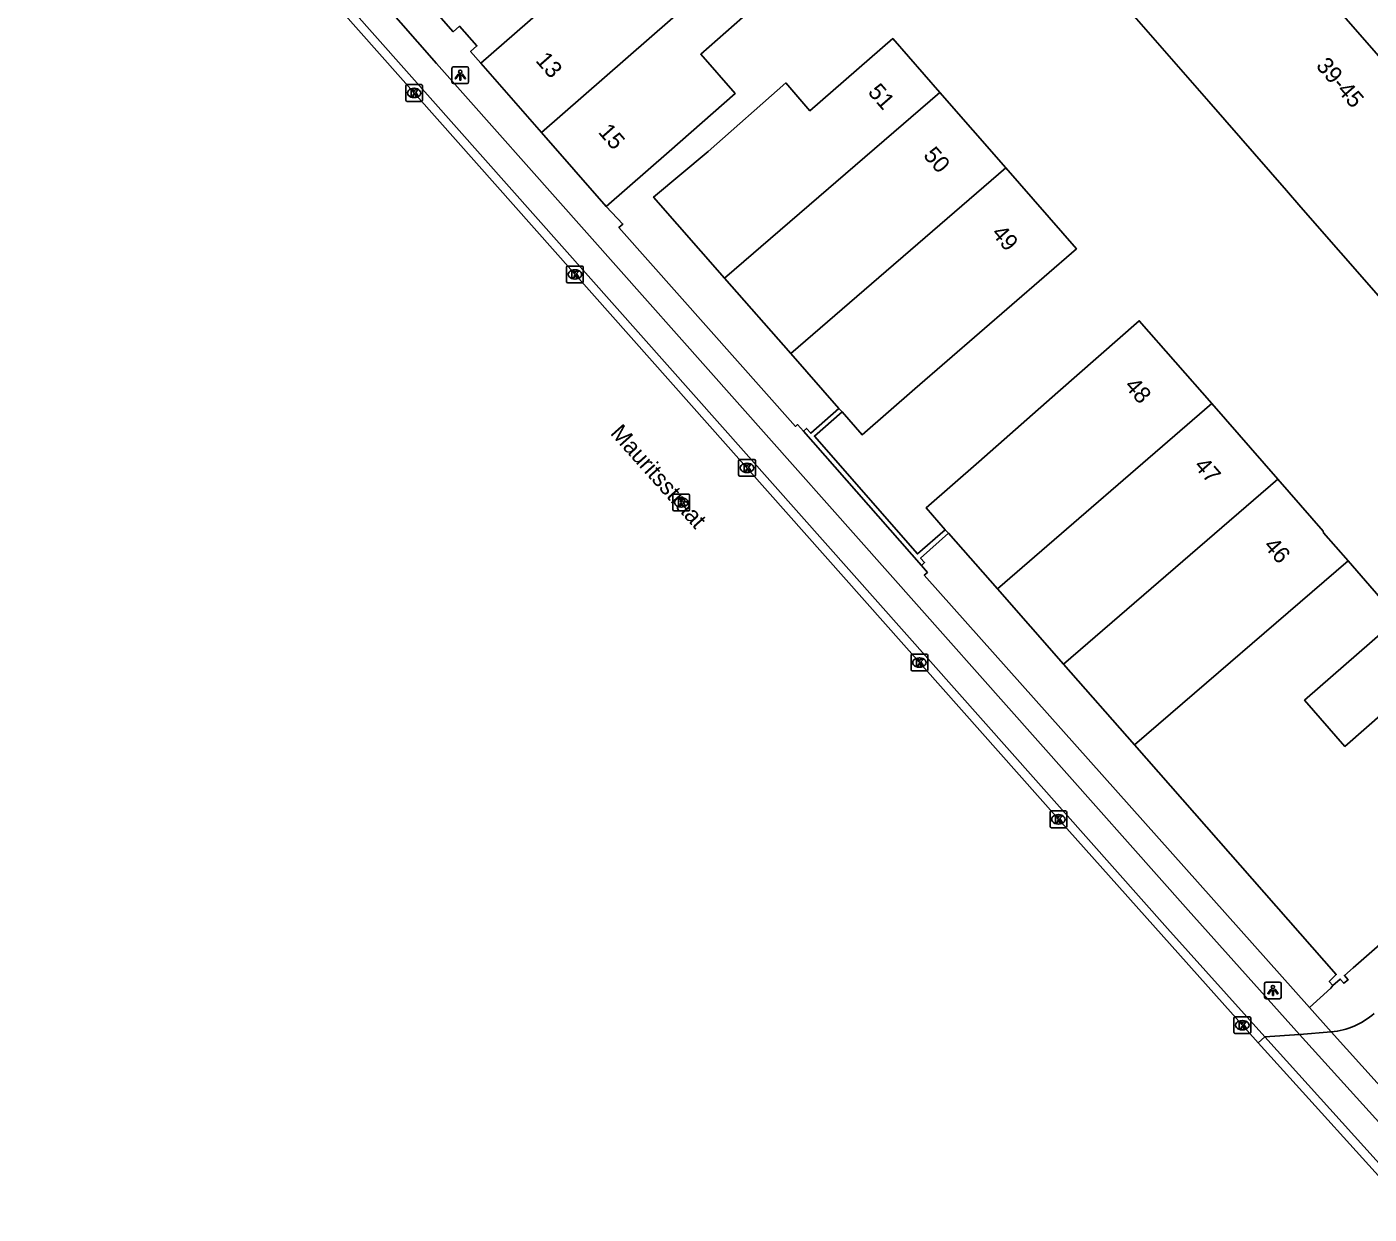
# Model space of a CAD drawing. Extents: x 160664 to 161506, y 382245 to 383288.
# Drawn here: x 160694.2 to 160774.6, y 383018.1 to 383089.2 of the extents above; entities that cross this region are included whole.
import ezdxf

# ---------------------------------------------------------------- set-up
doc = ezdxf.new("R2010")
doc.units = 0
for name, color, linetype in [('IMGEO_Berm_gesloten', 7, 'Continuous'), ('IMGEO_Fietspad_gesloten', 7, 'Continuous'), ('IMGEO_Kolk', 7, 'Continuous'), ('IMGEO_Lichtpunt', 7, 'Continuous'), ('IMGEO_Muur', 7, 'Continuous'), ('IMGEO_Openbare_ruimte_label', 7, 'Continuous'), ('IMGEO_Pand', 7, 'Continuous'), ('IMGEO_Pand_nummerreeks', 7, 'Continuous'), ('IMGEO_Rijbaan_lokaal_gesloten', 7, 'Continuous'), ('IMGEO_Rijbaan_lokaal_open', 7, 'Continuous'), ('IMGEO_Rioolput', 7, 'Continuous'), ('IMGEO_Voetpad_open', 7, 'Continuous')]:
    doc.layers.add(name, color=color, linetype=linetype)

msp = doc.modelspace()

# ---------------------------------------------------------------- linework, layer by layer
at = {"layer": 'IMGEO_Berm_gesloten'}
msp.add_lwpolyline([(160768.358, 383028.694), (160767.962, 383028.335)], dxfattribs=at)
at = {"layer": 'IMGEO_Fietspad_gesloten'}
for points in [[(160770.443, 383028.844), (160763.764, 383036.278), (160718.771, 383086.968), (160703.534, 383104.351), (160702.367, 383105.793), (160696.071, 383113.574)], [(160768.358, 383028.694), (160762.53, 383035.176), (160707.345, 383097.37), (160702.219, 383103.325), (160701.082, 383104.713), (160699.114, 383107.117), (160694.239, 383113.304)], [(160770.443, 383028.844), (160768.358, 383028.694)], [(160777.628, 383018.442), (160768.358, 383028.694)], [(160770.443, 383028.844), (160777.267, 383021.287)]]:
    msp.add_lwpolyline(points, dxfattribs=at)
at = {"layer": 'IMGEO_Kolk'}
for p, q in [((160716.927, 383084.785), (160716.927, 383085.637)), ((160717.002, 383085.711), (160717.854, 383085.711)), ((160717.415, 383085.491), (160717.44, 383085.491)), ((160717.928, 383085.637), (160717.928, 383084.785)), ((160717.854, 383084.711), (160717.002, 383084.711)), ((160717.438, 383084.931), (160717.413, 383084.931)), ((160726.629, 383074.851), (160727.481, 383074.851)), ((160726.554, 383073.925), (160726.554, 383074.777)), ((160727.065, 383074.071), (160727.04, 383074.071)), ((160727.042, 383074.631), (160727.067, 383074.631)), ((160727.555, 383074.777), (160727.555, 383073.925)), ((160727.481, 383073.851), (160726.629, 383073.851)), ((160736.856, 383062.34), (160736.856, 383063.192)), ((160736.931, 383063.266), (160737.783, 383063.266)), ((160737.344, 383063.046), (160737.369, 383063.046)), ((160737.857, 383063.192), (160737.857, 383062.34)), ((160737.783, 383062.266), (160736.931, 383062.266)), ((160737.367, 383062.486), (160737.342, 383062.486)), ((160747.18, 383050.681), (160747.18, 383051.533)), ((160747.255, 383051.607), (160748.107, 383051.607)), ((160748.181, 383051.533), (160748.181, 383050.681)), ((160747.691, 383050.827), (160747.666, 383050.827)), ((160747.668, 383051.387), (160747.693, 383051.387)), ((160748.107, 383050.607), (160747.255, 383050.607)), ((160755.501, 383041.295), (160755.501, 383042.147)), ((160755.576, 383042.221), (160756.428, 383042.221)), ((160755.989, 383042.001), (160756.014, 383042.001)), ((160756.502, 383042.147), (160756.502, 383041.295)), ((160756.428, 383041.221), (160755.576, 383041.221)), ((160756.012, 383041.441), (160755.987, 383041.441)), ((160766.511, 383028.967), (160766.511, 383029.819)), ((160766.586, 383029.893), (160767.438, 383029.893)), ((160767.512, 383029.819), (160767.512, 383028.967)), ((160767.022, 383029.113), (160766.997, 383029.113)), ((160766.999, 383029.673), (160767.024, 383029.673)), ((160767.438, 383028.893), (160766.586, 383028.893))]:
    msp.add_line(p, q, dxfattribs=at)
for points in [[(160716.927, 383084.785), (160716.927, 383085.637)], [(160717.002, 383085.711), (160717.854, 383085.711)], [(160717.248, 383085.411), (160717.371, 383085.411), (160717.371, 383085.26), (160717.501, 383085.411), (160717.665, 383085.411), (160717.519, 383085.26), (160717.672, 383085.011), (160717.52, 383085.011), (160717.435, 383085.175), (160717.371, 383085.108), (160717.371, 383085.011), (160717.248, 383085.011), (160717.248, 383085.411)], [(160717.928, 383085.637), (160717.928, 383084.785)], [(160717.854, 383084.711), (160717.002, 383084.711)], [(160726.629, 383074.851), (160727.481, 383074.851)], [(160726.554, 383073.925), (160726.554, 383074.777)], [(160726.875, 383074.551), (160726.998, 383074.551), (160726.998, 383074.4), (160727.128, 383074.551), (160727.292, 383074.551), (160727.146, 383074.4), (160727.299, 383074.151), (160727.147, 383074.151), (160727.062, 383074.315), (160726.998, 383074.248), (160726.998, 383074.151), (160726.875, 383074.151), (160726.875, 383074.551)], [(160727.555, 383074.777), (160727.555, 383073.925)], [(160727.481, 383073.851), (160726.629, 383073.851)], [(160736.856, 383062.34), (160736.856, 383063.192)], [(160736.931, 383063.266), (160737.783, 383063.266)], [(160737.177, 383062.966), (160737.3, 383062.966), (160737.3, 383062.815), (160737.43, 383062.966), (160737.594, 383062.966), (160737.448, 383062.815), (160737.601, 383062.566), (160737.449, 383062.566), (160737.364, 383062.73), (160737.3, 383062.663), (160737.3, 383062.566), (160737.177, 383062.566), (160737.177, 383062.966)], [(160737.857, 383063.192), (160737.857, 383062.34)], [(160737.783, 383062.266), (160736.931, 383062.266)], [(160747.18, 383050.681), (160747.18, 383051.533)], [(160747.255, 383051.607), (160748.107, 383051.607)], [(160748.181, 383051.533), (160748.181, 383050.681)], [(160747.501, 383051.307), (160747.624, 383051.307), (160747.624, 383051.156), (160747.754, 383051.307), (160747.918, 383051.307), (160747.772, 383051.156), (160747.925, 383050.907), (160747.773, 383050.907), (160747.688, 383051.071), (160747.624, 383051.004), (160747.624, 383050.907), (160747.501, 383050.907), (160747.501, 383051.307)], [(160748.107, 383050.607), (160747.255, 383050.607)], [(160755.501, 383041.295), (160755.501, 383042.147)], [(160755.576, 383042.221), (160756.428, 383042.221)], [(160755.822, 383041.921), (160755.945, 383041.921), (160755.945, 383041.77), (160756.075, 383041.921), (160756.239, 383041.921), (160756.093, 383041.77), (160756.246, 383041.521), (160756.094, 383041.521), (160756.009, 383041.685), (160755.945, 383041.618), (160755.945, 383041.521), (160755.822, 383041.521), (160755.822, 383041.921)], [(160756.502, 383042.147), (160756.502, 383041.295)], [(160756.428, 383041.221), (160755.576, 383041.221)], [(160766.511, 383028.967), (160766.511, 383029.819)], [(160766.586, 383029.893), (160767.438, 383029.893)], [(160767.512, 383029.819), (160767.512, 383028.967)], [(160766.832, 383029.593), (160766.955, 383029.593), (160766.955, 383029.442), (160767.085, 383029.593), (160767.249, 383029.593), (160767.103, 383029.442), (160767.256, 383029.193), (160767.104, 383029.193), (160767.019, 383029.357), (160766.955, 383029.29), (160766.955, 383029.193), (160766.832, 383029.193), (160766.832, 383029.593)], [(160767.438, 383028.893), (160766.586, 383028.893)]]:
    msp.add_lwpolyline(points, dxfattribs=at)
for centre, start, end in [((160717.004, 383085.635), 91.55205, 178.44795), ((160717.004, 383085.635), 91.55205, 178.44795), ((160717.852, 383085.635), 1.55205, 88.44795), ((160717.852, 383085.635), 1.55205, 88.44795), ((160717.004, 383084.787), 181.55205, 268.44795), ((160717.004, 383084.787), 181.55205, 268.44795), ((160717.852, 383084.787), 271.55205, 358.44795), ((160717.852, 383084.787), 271.55205, 358.44795), ((160726.631, 383074.775), 91.55205, 178.44795), ((160726.631, 383074.775), 91.55205, 178.44795), ((160727.479, 383074.775), 1.55205, 88.44795), ((160727.479, 383074.775), 1.55205, 88.44795), ((160726.631, 383073.927), 181.55205, 268.44795), ((160726.631, 383073.927), 181.55205, 268.44795), ((160727.479, 383073.927), 271.55205, 358.44795), ((160727.479, 383073.927), 271.55205, 358.44795), ((160736.933, 383063.19), 91.55205, 178.44795), ((160736.933, 383063.19), 91.55205, 178.44795), ((160737.781, 383063.19), 1.55205, 88.44795), ((160737.781, 383063.19), 1.55205, 88.44795), ((160736.933, 383062.342), 181.55205, 268.44795), ((160736.933, 383062.342), 181.55205, 268.44795), ((160737.781, 383062.342), 271.55205, 358.44795), ((160737.781, 383062.342), 271.55205, 358.44795), ((160747.257, 383051.531), 91.55205, 178.44795), ((160747.257, 383051.531), 91.55205, 178.44795), ((160748.105, 383051.531), 1.55205, 88.44795), ((160748.105, 383051.531), 1.55205, 88.44795), ((160747.257, 383050.683), 181.55205, 268.44795), ((160747.257, 383050.683), 181.55205, 268.44795), ((160748.105, 383050.683), 271.55205, 358.44795), ((160748.105, 383050.683), 271.55205, 358.44795), ((160755.578, 383042.145), 91.55205, 178.44795), ((160755.578, 383042.145), 91.55205, 178.44795), ((160756.426, 383042.145), 1.55205, 88.44795), ((160756.426, 383042.145), 1.55205, 88.44795), ((160755.578, 383041.297), 181.55205, 268.44795), ((160755.578, 383041.297), 181.55205, 268.44795), ((160756.426, 383041.297), 271.55205, 358.44795), ((160756.426, 383041.297), 271.55205, 358.44795), ((160766.588, 383029.817), 91.55205, 178.44795), ((160766.588, 383029.817), 91.55205, 178.44795), ((160767.436, 383029.817), 1.55205, 88.44795), ((160767.436, 383029.817), 1.55205, 88.44795), ((160766.588, 383028.969), 181.55205, 268.44795), ((160766.588, 383028.969), 181.55205, 268.44795), ((160767.436, 383028.969), 271.55205, 358.44795), ((160767.436, 383028.969), 271.55205, 358.44795)]:
    msp.add_arc(centre, 0.0765, start, end, dxfattribs=at)
for centre, major_axis, ratio, start_param, end_param in [((160717.414, 383085.211), (-0.387, 0.002), 0.722429, 4.712389, 7.853982), ((160717.439, 383085.211), (-0.39, 0.002), 0.717154, 1.570796, 4.712389), ((160727.041, 383074.351), (-0.387, 0.002), 0.722429, 4.712389, 7.853982), ((160727.066, 383074.351), (-0.39, 0.002), 0.717154, 1.570796, 4.712389), ((160737.343, 383062.766), (-0.387, 0.002), 0.722429, 4.712389, 7.853982), ((160737.368, 383062.766), (-0.39, 0.002), 0.717154, 1.570796, 4.712389), ((160747.667, 383051.107), (-0.387, 0.002), 0.722429, 4.712389, 7.853982), ((160747.692, 383051.107), (-0.39, 0.002), 0.717154, 1.570796, 4.712389), ((160755.988, 383041.721), (-0.387, 0.002), 0.722429, 4.712389, 7.853982), ((160756.013, 383041.721), (-0.39, 0.002), 0.717154, 1.570796, 4.712389), ((160766.998, 383029.393), (-0.387, 0.002), 0.722429, 4.712389, 7.853982), ((160767.023, 383029.393), (-0.39, 0.002), 0.717154, 1.570796, 4.712389)]:
    msp.add_ellipse(centre, major_axis=major_axis, ratio=ratio, start_param=start_param, end_param=end_param, dxfattribs=at)
at = {"layer": 'IMGEO_Lichtpunt'}
for p, q in [((160719.691, 383086.682), (160719.691, 383085.875)), ((160719.691, 383086.682), (160719.691, 383085.875)), ((160720.593, 383086.777), (160719.785, 383086.777)), ((160720.593, 383086.777), (160719.785, 383086.777)), ((160720.687, 383085.875), (160720.687, 383086.682)), ((160720.687, 383085.875), (160720.687, 383086.682)), ((160719.785, 383085.781), (160720.593, 383085.781)), ((160719.785, 383085.781), (160720.593, 383085.781)), ((160768.345, 383031.884), (160768.345, 383031.077)), ((160768.345, 383031.884), (160768.345, 383031.077)), ((160769.247, 383031.979), (160768.439, 383031.979)), ((160769.247, 383031.979), (160768.439, 383031.979)), ((160769.341, 383031.077), (160769.341, 383031.884)), ((160769.341, 383031.077), (160769.341, 383031.884)), ((160768.439, 383030.983), (160769.247, 383030.983)), ((160768.439, 383030.983), (160769.247, 383030.983))]:
    msp.add_line(p, q, dxfattribs=at)
for points in [[(160720.065, 383086.346), (160720.104, 383086.318), (160719.916, 383086.056), (160719.878, 383086.083), (160720.065, 383086.346)], [(160720.167, 383086.298), (160720.214, 383086.298), (160720.214, 383085.976), (160720.167, 383085.976), (160720.167, 383086.298)], [(160720.277, 383086.318), (160720.315, 383086.345), (160720.502, 383086.083), (160720.463, 383086.055), (160720.277, 383086.318)], [(160768.719, 383031.548), (160768.758, 383031.52), (160768.57, 383031.258), (160768.532, 383031.285), (160768.719, 383031.548)], [(160768.821, 383031.5), (160768.868, 383031.5), (160768.868, 383031.178), (160768.821, 383031.178), (160768.821, 383031.5)], [(160768.931, 383031.52), (160768.969, 383031.547), (160769.156, 383031.285), (160769.117, 383031.257), (160768.931, 383031.52)]]:
    msp.add_lwpolyline(points, dxfattribs=at)
for centre in [(160720.19, 383086.48), (160768.844, 383031.682)]:
    msp.add_circle(centre, 0.0994, dxfattribs=at)
for centre, start, end in [((160719.785, 383086.682), 90, 180), ((160719.785, 383086.682), 90, 180), ((160720.593, 383086.682), 0, 90), ((160720.593, 383086.682), 0, 90), ((160719.785, 383085.875), 180, 270), ((160719.785, 383085.875), 180, 270), ((160720.593, 383085.875), 270, 0), ((160720.593, 383085.875), 270, 360), ((160768.439, 383031.884), 90, 180), ((160768.439, 383031.884), 90, 180), ((160769.247, 383031.884), 0, 90), ((160769.247, 383031.884), 0, 90), ((160768.439, 383031.077), 180, 270), ((160768.439, 383031.077), 180, 270), ((160769.247, 383031.077), 270, 0), ((160769.247, 383031.077), 270, 360)]:
    msp.add_arc(centre, 0.0946, start, end, dxfattribs=at)
at = {"layer": 'IMGEO_Muur'}
for points in [[(160740.73, 383064.964), (160740.918, 383065.129), (160741.176, 383064.836), (160742.859, 383066.32)], [(160743.052, 383066.116), (160741.394, 383064.67), (160747.56, 383057.614), (160749.218, 383059.06)], [(160747.804, 383056.924), (160740.73, 383064.964)], [(160749.42, 383058.859), (160747.748, 383057.366), (160747.992, 383057.089), (160747.804, 383056.924)]]:
    msp.add_lwpolyline(points, dxfattribs=at)
at = {"layer": 'IMGEO_Pand'}
for points in [[(160764.255, 383099.938), (160757.448, 383093.999), (160756.804, 383094.737), (160756.48, 383094.454), (160765.001, 383084.7), (160769.663, 383079.367), (160770.523, 383078.382), (160782.34, 383064.863), (160791.941, 383073.242), (160789.444, 383076.109), (160786.953, 383073.958), (160764.255, 383099.938)], [(160729.178, 383093.784), (160721.42, 383086.995)], [(160716.745, 383092.325), (160719.77, 383088.881), (160720.146, 383089.211), (160721.181, 383088.028), (160720.804, 383087.699), (160721.42, 383086.995)], [(160725.052, 383082.849), (160735.275, 383091.796)], [(160735.275, 383091.796), (160737.087, 383089.725), (160734.582, 383087.533), (160736.644, 383085.178), (160732.69, 383081.717), (160728.928, 383078.423)], [(160748.895, 383085.247), (160746.079, 383088.471), (160741.125, 383084.148), (160739.68, 383085.812), (160735.027, 383081.714), (160731.764, 383078.977), (160736.016, 383074.127)], [(160721.42, 383086.995), (160725.052, 383082.849)], [(160736.016, 383074.127), (160748.895, 383085.247)], [(160748.895, 383085.247), (160752.843, 383080.728)], [(160725.052, 383082.849), (160728.928, 383078.423)], [(160752.843, 383080.728), (160739.971, 383069.614)], [(160743.052, 383066.116), (160744.241, 383064.752), (160747.401, 383067.493), (160757.076, 383075.883), (160752.843, 383080.728)], [(160739.971, 383069.614), (160736.016, 383074.127)], [(160749.218, 383059.06), (160748.08, 383060.364), (160751.236, 383063.118), (160755.975, 383067.307), (160760.845, 383071.574), (160765.185, 383066.611)], [(160739.971, 383069.614), (160742.859, 383066.32)], [(160742.859, 383066.32), (160743.052, 383066.116)], [(160765.185, 383066.611), (160752.347, 383055.527)], [(160765.185, 383066.611), (160769.134, 383062.095)], [(160769.134, 383062.095), (160756.307, 383051.019)], [(160769.134, 383062.095), (160771.856, 383058.982), (160771.879, 383058.88), (160773.339, 383057.204)], [(160749.218, 383059.06), (160749.42, 383058.859)], [(160749.42, 383058.859), (160752.347, 383055.527)], [(160773.339, 383057.204), (160760.563, 383046.173)], [(160782.484, 383054.246), (160781.278, 383053.198), (160773.152, 383046.089), (160770.736, 383048.852), (160776.347, 383053.751), (160773.339, 383057.204)], [(160752.347, 383055.527), (160756.307, 383051.019)], [(160756.307, 383051.019), (160760.563, 383046.173)], [(160760.563, 383046.173), (160772.635, 383032.43), (160772.216, 383032.016), (160772.432, 383031.763)], [(160788.84, 383046.396), (160787.902, 383045.586), (160788.374, 383045.042), (160785.404, 383042.466), (160785.093, 383042.838), (160773.657, 383032.835), (160773.126, 383032.378), (160773.344, 383032.118), (160773.088, 383031.903), (160772.871, 383032.154), (160772.432, 383031.763)]]:
    msp.add_lwpolyline(points, dxfattribs=at)
at = {"layer": 'IMGEO_Rijbaan_lokaal_gesloten'}
for points in [[(160767.962, 383028.335), (160756.002, 383041.721), (160707.188, 383096.777), (160701.821, 383103.003), (160700.685, 383104.38), (160698.642, 383106.855), (160694.714, 383111.885)], [(160777.232, 383018.081), (160767.962, 383028.335)]]:
    msp.add_lwpolyline(points, dxfattribs=at)
at = {"layer": 'IMGEO_Rijbaan_lokaal_open'}
msp.add_lwpolyline([(160772.34, 383028.989), (160776.924, 383023.917)], dxfattribs=at)
msp.add_arc((160771.915, 383033.484), 4.515, 275.40339, 311.4728, dxfattribs=at)
at = {"layer": 'IMGEO_Rioolput'}
for p, q in [((160732.992, 383061.198), (160733.844, 383061.198)), ((160732.917, 383060.272), (160732.917, 383061.124)), ((160733.428, 383060.418), (160733.403, 383060.418)), ((160733.405, 383060.978), (160733.43, 383060.978)), ((160733.918, 383061.124), (160733.918, 383060.272)), ((160733.844, 383060.198), (160732.992, 383060.198))]:
    msp.add_line(p, q, dxfattribs=at)
for points in [[(160732.992, 383061.198), (160733.844, 383061.198)], [(160732.917, 383060.272), (160732.917, 383061.124)], [(160733.506, 383060.896), (160733.254, 383060.898), (160733.254, 383060.498)], [(160733.254, 383060.498), (160733.378, 383060.498), (160733.378, 383060.66), (160733.389, 383060.66)], [(160733.432, 383060.817), (160733.378, 383060.817), (160733.378, 383060.736)], [(160733.378, 383060.736), (160733.43, 383060.736)], [(160733.436, 383060.631), (160733.507, 383060.498), (160733.647, 383060.498), (160733.582, 383060.624)], [(160733.918, 383061.124), (160733.918, 383060.272)], [(160733.844, 383060.198), (160732.992, 383060.198)]]:
    msp.add_lwpolyline(points, dxfattribs=at)
for centre, radius, start, end in [((160732.994, 383061.122), 0.0765, 91.55205, 178.44795), ((160732.994, 383061.122), 0.0765, 91.55205, 178.44795), ((160733.842, 383061.122), 0.0765, 1.55205, 88.44795), ((160733.842, 383061.122), 0.0765, 1.55205, 88.44795), ((160733.388, 383060.607), 0.0533, 26.02933, 88.69889), ((160733.414, 383060.925), 0.19, 274.7715, 282.96867), ((160733.438, 383060.721), 0.0964, 77.00612, 93.18647), ((160733.452, 383060.778), 0.0378, 276.66336, 79.67722), ((160733.505, 383060.786), 0.109, 350.36119, 89.41601), ((160733.503, 383060.786), 0.112, 277.58423, 350.98172), ((160733.487, 383060.571), 0.108, 29.51342, 73.79051), ((160732.994, 383060.274), 0.0765, 181.55205, 268.44795), ((160732.994, 383060.274), 0.0765, 181.55205, 268.44795), ((160733.842, 383060.274), 0.0765, 271.55205, 358.44795), ((160733.842, 383060.274), 0.0765, 271.55205, 358.44795)]:
    msp.add_arc(centre, radius, start, end, dxfattribs=at)
for centre, major_axis, ratio, start_param, end_param in [((160733.404, 383060.698), (-0.387, 0.002), 0.722429, 4.712389, 7.853982), ((160733.429, 383060.698), (-0.39, 0.002), 0.717154, 1.570796, 4.712389)]:
    msp.add_ellipse(centre, major_axis=major_axis, ratio=ratio, start_param=start_param, end_param=end_param, dxfattribs=at)
at = {"layer": 'IMGEO_Voetpad_open'}
for points in [[(160728.928, 383078.423), (160729.93, 383077.362), (160729.683, 383077.158), (160740.251, 383065.247), (160740.378, 383065.36), (160740.73, 383064.964)], [(160771.029, 383030.453), (160747.966, 383056.336), (160748.161, 383056.502), (160747.804, 383056.924)], [(160772.432, 383031.763), (160772.306, 383031.61), (160771.029, 383030.453)], [(160771.029, 383030.453), (160772.34, 383028.989)], [(160772.34, 383028.989), (160770.443, 383028.844)]]:
    msp.add_lwpolyline(points, dxfattribs=at)

# ---------------------------------------------------------------- texts
at = {"layer": 'IMGEO_Openbare_ruimte_label'}
msp.add_text('Mauritsstraat', height=1, rotation=311.75725, dxfattribs=at).set_placement((160729.125, 383064.815))
at = {"layer": 'IMGEO_Pand_nummerreeks'}
for s, rotation, p in [('13', 311.21215, (160724.648, 383087.136)), ('39-45', 311.1428, (160771.373, 383086.805)), ('51', 311.14078, (160744.548, 383085.238)), ('15', 311.21215, (160728.402, 383082.85)), ('50', 311.25457, (160747.864, 383081.449)), ('49', 311.03466, (160751.946, 383076.779)), ('48', 311.00535, (160759.913, 383067.648)), ('47', 311.00535, (160764.075, 383062.861)), ('46', 311.00535, (160768.24, 383058.071))]:
    msp.add_text(s, height=1, rotation=rotation, dxfattribs=at).set_placement(p)

doc.saveas('drawing.dxf')
